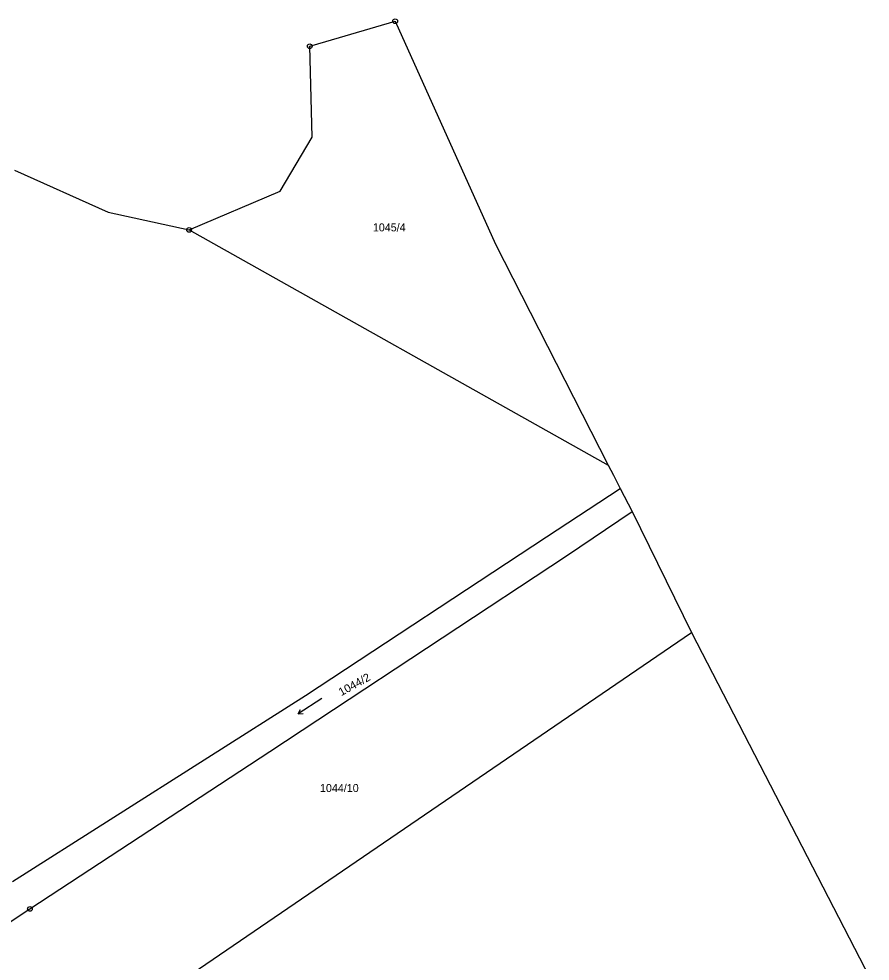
# Model space of a CAD drawing. Extents: x -694609 to -690140, y -1033292 to -1029794.
# Drawn here: x -690725.9 to -690545, y -1031744.2 to -1031544 of the extents above; entities that cross this region are included whole.
import ezdxf
from ezdxf.enums import TextEntityAlignment as Align

# ---------------------------------------------------------------- set-up
doc = ezdxf.new("R2010")
doc.units = 0
doc.header["$LTSCALE"] = 0.68
for name, color, linetype, lineweight in [('1', 7, 'Continuous', 25), ('3', 7, 'Continuous', 25), ('8', 7, 'Continuous', 25)]:
    doc.layers.add(name, color=color, linetype=linetype, lineweight=lineweight)
doc.layers.add('2', color=7, linetype='Continuous')

msp = doc.modelspace()

# ---------------------------------------------------------------- linework, layer by layer
at = {"layer": '1'}
for p, q in [((-690660.63, -1031548.85), (-690645.91, -1031544.54)), ((-690645.91, -1031544.54), (-690624.61, -1031591.92)), ((-690664.07, -1031549.86), (-690660.63, -1031548.85)), ((-690663.52, -1031569.16), (-690664.07, -1031549.86)), ((-690670.32, -1031580.68), (-690663.52, -1031569.16)), ((-690726.81, -1031576.22), (-690706.91, -1031585.09)), ((-690689.68, -1031588.88), (-690670.32, -1031580.68)), ((-690706.91, -1031585.09), (-690689.68, -1031588.88)), ((-690689.68, -1031588.88), (-690600.66, -1031638.85)), ((-690624.61, -1031591.92), (-690600.66, -1031638.85)), ((-690600.66, -1031638.85), (-690599.56, -1031641)), ((-690599.56, -1031641), (-690598.12, -1031643.82)), ((-690613.74, -1031654.12), (-690598.12, -1031643.82)), ((-690609.48, -1031658.11), (-690595.57, -1031648.71)), ((-690664.94, -1031687.82), (-690613.74, -1031654.12)), ((-690662.34, -1031692.99), (-690609.48, -1031658.11)), ((-690712.47, -1031762.82), (-690582.95, -1031674.44)), ((-690582.95, -1031674.44), (-690545, -1031747.94)), ((-690727.23, -1031727.32), (-690664.94, -1031687.82)), ((-690672.57, -1031699.69), (-690662.34, -1031692.99)), ((-690723.5, -1031733.14), (-690672.57, -1031699.69)), ((-690727.72, -1031735.91), (-690723.5, -1031733.14))]:
    msp.add_line(p, q, dxfattribs=at)
msp.add_lwpolyline([(-690598.12, -1031643.82), (-690595.57, -1031648.71), (-690582.95, -1031674.44)], dxfattribs=at)
at = {"layer": '3'}
msp.add_line((-690666.535, -1031691.726), (-690665.989, -1031690.773), dxfattribs=at)
msp.add_lwpolyline([(-690661.503, -1031688.458), (-690666.535, -1031691.726), (-690665.442, -1031691.614)], dxfattribs=at)
at = {"layer": '8'}
for centre, radius in [((-690645.91, -1031544.5399), 0.5), ((-690645.91, -1031544.5399), 0.0303), ((-690664.07, -1031549.8599), 0.5), ((-690664.07, -1031549.8599), 0.0303), ((-690689.68, -1031588.8799), 0.5), ((-690689.68, -1031588.8799), 0.0303), ((-690723.5, -1031733.1399), 0.5), ((-690723.5, -1031733.1399), 0.0303)]:
    msp.add_circle(centre, radius, dxfattribs=at)

# ---------------------------------------------------------------- texts
at = {"layer": '2'}
for s, p in [('1045/4', (-690647.17, -1031589.195)), ('1044/10', (-690657.769, -1031708.305))]:
    msp.add_text(s, height=1.7, dxfattribs=at).set_placement(p, align=Align.CENTER)
at = {"layer": '2', "width": 1.05}
msp.add_text('1044/2', height=1.7, rotation=29, dxfattribs=at).set_placement((-690654.1731, -1031686.195), align=Align.CENTER)

doc.saveas('drawing.dxf')
